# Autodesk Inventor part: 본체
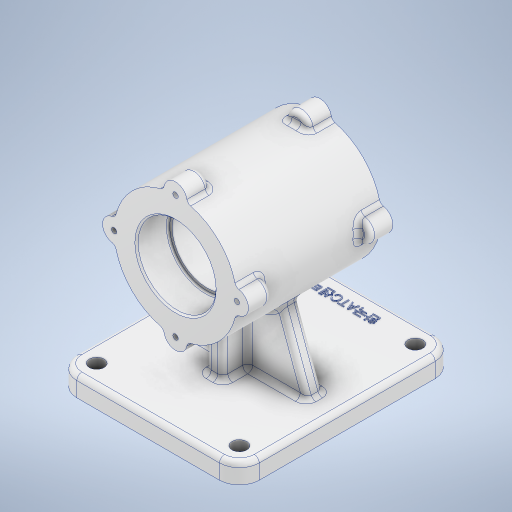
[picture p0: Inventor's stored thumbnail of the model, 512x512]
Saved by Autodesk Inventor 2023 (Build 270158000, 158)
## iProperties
Created: 2023-08
Part Number: 본체
Material: 알루미늄 6061
Document SubType Name: Modeling
Designer: asung
Density: 2.7 g/cm^3
Appearance: 알루미늄 - 평지
Author: asung
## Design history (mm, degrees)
sketch "스케치1"
  geometry: L1 (-43, -65)-(43, -65); L2 (55, -53)-(55, 53); L3 (43, 65)-(-43, 65); L4 (-55, 53)-(-55, -53); L5 (-55, -65)-(55, 65); L6 (55, -65)-(-55, 65); C1 r 4.5 at (43, 53); C2 r 4.5 at (43, -53); C3 r 4.5 at (-43, -53); C4 r 4.5 at (-43, 53); A1 r 12 centre (43, 53) between (55, 53) and (43, 65); A2 r 12 centre (43, -53) between (43, -65) and (55, -53); A3 r 12 centre (-43, -53) between (-55, -53) and (-43, -65); A4 r 12 centre (-43, 53) between (-43, 65) and (-55, 53); 1 further point
  constraints: 12 end point, 8 centre point, 8 point on circle, 8 point on line, 8 tangent, 4 coincident, 3 equal radius, 2 midpoint, 2 parallel, 1 horizontal, 1 perpendicular
  dimensions: "d0" = 110 distance of L6.end L5.end; "d1" = 130 distance of L5.end L6.start; "d2" = 12 radius of A1; "d3" = 9 diameter of C1; "d4" = 9 diameter of C2; "d5" = 9 diameter of C3; "d6" = 9 diameter of C4
extrude "돌출1" new body sketch "스케치1" distance "d7" = 12; taper "d8" = 0 deg
node "작업 평면3"
sketch "스케치4"
  geometry: L1 (-12, 0)-(-12, 12) reference; L2 (-12, 12)-(118, 12) reference; L3 (118, 12)-(118, 0) reference; L4 (118, 0)-(-12, 0) reference; L5 (118, 0)-(106, 0) reference; L6 (118, 0)-(48, 0); L7 (0, 0)-(106, 0) reference; L8 (48, 0)-(48, 82); L9 (91.5, 82)-(4.5, 82); L10 (91.5, 82)-(91.5, 119); L11 (91.5, 119)-(4.5, 119); L12 (4.5, 119)-(4.5, 82); 1 further point
  constraints: 12 end point, 2 perpendicular, 2 vertical, 1 horizontal, 1 midpoint, 1 point on line
  dimensions: "d19" = 70 distance of L3.end L6.end; "d20" = 82 distance of L8.end L6.end; "d21" = 87 distance of L9.start L9.end; "d22" = 37 distance of L9.start L10.end
revolve "회전2" sketch "스케치4" stored, may be unused: angle "d23" = 90 deg
sketch "스케치5"
  geometry: C1 r 7 at (0, 37); 4 further points
  constraints: 1 centre point, 2 other
  dimensions: "d24" = 7 radius of C1
extrude "돌출2" join sketch "스케치5" distance "d25" = 14; taper "d26" = 0 deg
fillet "모깎기1" dims "d27" = 3
fillet "모깎기2" dims "d28" = 3
sketch "스케치6"
  geometry: A1 r 7 centre (0, 0) between (6.889, 1.239) and (-6.889, 1.239) reference; 2 further points
  constraints: 1 coincident
hole "구멍1" sketch "스케치6" at (0, 0) diameter "d29" = 3.242; stored, may be unused: countersink angle "d33" = 90 deg, drill point angle "d35" = 118 deg; dims "d30" = 8, "d31" = 4, "d32" = 2, "d34" = 10
node "작업 평면4"
sketch "스케치7"
  geometry: A1 r 37 centre (0, -37) between (-35.863, -46.104) and (-9.104, -72.862) reference; 2 further points
  constraints: 1 coincident
hole "구멍2" sketch "스케치7" at (0, -37) diameter "d42" = 42; stored, may be unused: countersink angle "d46" = 90 deg, drill point angle "d48" = 118 deg; dims "d43" = 8, "d44" = 47, "d45" = 19, "d47" = 80
sketch "스케치8"
  geometry: A1 r 37 centre (0, 37) between (35.863, 46.104) and (9.104, 72.862) reference; 2 further points
  constraints: 1 coincident
hole "구멍3" sketch "스케치8" at (0, 37) diameter "d49" = 42; stored, may be unused: countersink angle "d53" = 90 deg, drill point angle "d55" = 118 deg; dims "d50" = 6, "d51" = 47, "d52" = 19, "d54" = 80
fillet "모깎기3" dims "d56" = 1
chamfer "모따기1" distance "d57" = 1; stored, may be unused: second distance "d58" = 2, angle "d59" = 45 deg
sketch "스케치9"
  geometry: L1 (68, 47.769)-(28, 47.769); L2 (28, 47.769)-(28, 6.256); L3 (28, 6.256)-(68, 6.256); L4 (68, 6.256)-(68, 47.769); L5 (118, 0)-(118, 12) reference; 2 further points
  constraints: 8 end point, 2 parallel, 1 horizontal, 1 midpoint, 1 perpendicular
  dimensions: "d60" = 40 distance of L2.end L3.end; "d61" = 50 distance from line of point (118, 6) L4
extrude "돌출3" join sketch "스케치9" stored distance "d62" = 10; taper "d63" = 0 deg
node "작업 평면5"
sketch "스케치10"
  geometry: L1 (55, -107)-(55, -119) reference; L2 (55, -119)-(-55, -119) reference; L3 (-55, -119)-(-55, -107) reference; L4 (-55, -107)-(-5, -107) reference; L5 (-5, -107)-(-5, -73.661) reference; L6 (5, -73.661)-(5, -107) reference; L7 (5, -107)-(55, -107) reference; L8 (-55, -107)-(-41, -107); L9 (-47.5, -107)-(-38.5, -107) reference; L10 (-41, -107)-(-23.247, -58.223); L11 (55, -107)-(41, -107); L12 (38.5, -107)-(47.5, -107) reference; L13 (41, -107)-(23.247, -58.223); L14 (-23.247, -58.223)-(-6.445, -67.354); L15 (-6.445, -67.354)-(23.247, -58.223); C1 r 21 at (0, -37) reference; A1 r 37 centre (0, -37) between (5, -73.661) and (-5, -73.661) reference; 4 further points
  constraints: 12 end point, 2 point on line, 1 midpoint
  dimensions: "d64" = 14 distance of L3.end L8.end; "d65" = 110 deg angle of L4 L10; "d66" = 14 distance of L1.start L11.end; "d68" = 110 deg angle of L11 L13
extrude "돌출4" join sketch "스케치10" stored distance "d69" = 10; taper "d70" = 0 deg
fillet "모깎기4" dims "d71" = 3
fillet "모깎기5" dims "d72" = 3
fillet "모깎기6" dims "d73" = 3
fillet "모깎기7" dims "d74" = 3
sketch "스케치11"
  geometry: L1 (-43, -65)-(43, -65) reference; 2 further points
  constraints: 1 other
  dimensions: "d75" = 118 distance from line of L1 point (0, 53)
feature "엠보싱1" sketch "스케치11" dims "d0" = 110, "d1" = 130, "d2" = 12, "d3" = 9, "d4" = 9, "d5" = 9, "d6" = 9, "d76" = 0.5, "d77" = 0
feature "Ύ耀ΐ耀Β耀Δ耀Ζ耀Θ耀Κ耀Μ耀" dims "d0" = 110, "d1" = 130, "d2" = 12, "d3" = 9, "d4" = 9, "d5" = 9, "d6" = 9, "d7" = 12, "d8" = 0, "d19" = 70, "d20" = 82, "d21" = 87, "d22" = 37, "d23" = 90 deg, "d24" = 7, "d25" = 14, "d26" = 0, "d27" = 3, "d28" = 3, "d29" = 3.242, "d30" = 8, "d31" = 4, "d32" = 2, "d33" = 90 deg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
node "솔리드1"
pattern_circular "원형 패턴1" dims angle "d37" = 360 deg
pattern_circular "원형 패턴2" dims "d40" = 360 deg
mirror "미러1"
node "투영된 루프1"
node "절단 모서리 투영3"
node "절단 모서리 투영4"
feature "A9D066F2-1C7D-4E18-AEED-F7BC21143FA4" dims "d42" = 42, "d43" = 8, "d44" = 47, "d45" = 19, "d46" = 90 deg, "d47" = 80, "d48" = 118 deg
